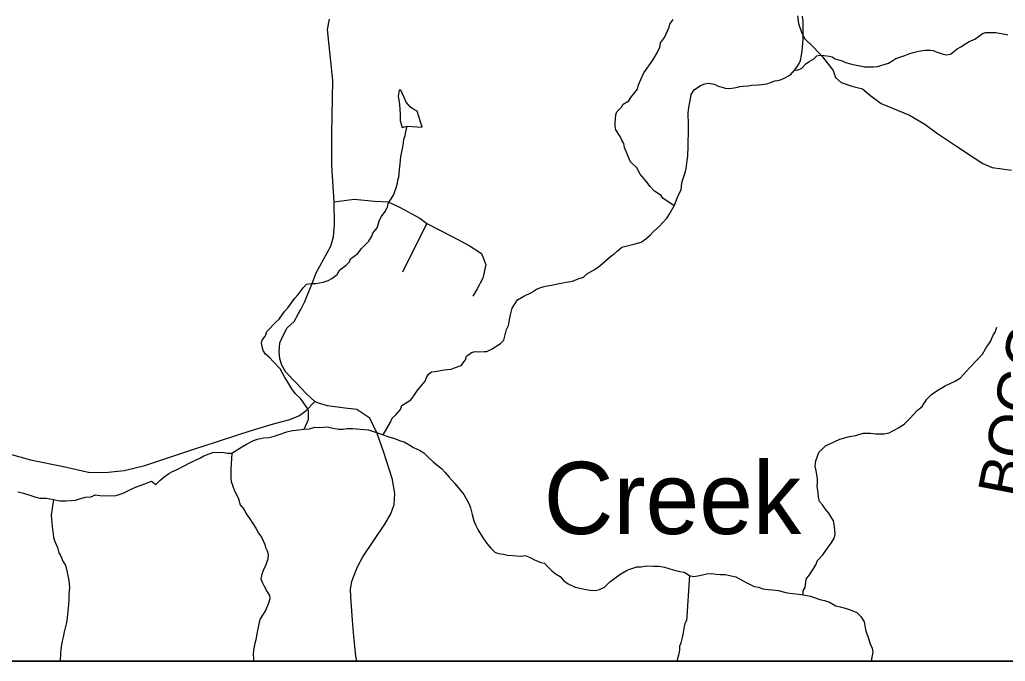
# Model space of a CAD drawing. Extents: x 0 to 39.3, y -3.9 to 22.
# Drawn here: x 4.806 to 6.099, y 13.9 to 14.741 of the extents above; entities that cross this region are included whole.
import ezdxf

# ---------------------------------------------------------------- set-up
doc = ezdxf.new("R2010")
doc.units = 0
for name, color, linetype in [('GM_X_Corporation', 7, 'Continuous'), ('GM_X_County_Road', 7, 'Continuous'), ('GM_X_Minor_Lake', 7, 'Continuous'), ('GM_X_Minor_River', 7, 'Continuous'), ('GM_X_Minor_River_Text', 7, 'Continuous'), ('GM_X_Township_Road', 7, 'Continuous'), ('GM_X_Township_Road_Text', 7, 'Continuous'), ('SH_Data', 7, 'Continuous')]:
    doc.layers.add(name, color=color, linetype=linetype)

msp = doc.modelspace()

# ---------------------------------------------------------------- linework, layer by layer
at = {"layer": 'GM_X_Corporation'}
msp.add_lwpolyline([(6.2667, 17.3782), (6.0256, 17.0319), (5.8398, 16.7652), (5.744, 16.6289), (5.7424, 16.6266), (5.2028, 15.8376), (5.0728, 15.652), (4.2376, 14.4362), (4.2334, 14.4302), (3.9536, 14.0228), (3.9474, 14.0138), (3.8692, 13.9), (7.894, 13.9)], dxfattribs=at)
at = {"layer": 'GM_X_County_Road'}
for points in [[(5.8265, 14.7467), (5.8278, 14.7364), (5.832, 14.724), (5.8363, 14.7165), (5.8473, 14.7053), (5.8593, 14.693), (5.8731, 14.6749), (5.8765, 14.6658), (5.8837, 14.659), (5.8977, 14.6544), (5.912, 14.6507), (5.9229, 14.6416), (5.9361, 14.6316), (5.9736, 14.6161), (5.9938, 14.6044), (6.0089, 14.5933), (6.0338, 14.5765), (6.0584, 14.5603), (6.0698, 14.5531), (6.0819, 14.5477), (6.1075, 14.544)], [(5.2484, 13.9), (5.2469, 13.9068), (5.2444, 13.9324), (5.2427, 13.9535), (5.2404, 13.9846), (5.2401, 13.9946), (5.2418, 14.0046), (5.2449, 14.0128), (5.2492, 14.0237), (5.2561, 14.0368), (5.2849, 14.0798), (5.2931, 14.0932), (5.2974, 14.1055), (5.2983, 14.1195), (5.2951, 14.1383), (5.2834, 14.1751), (5.2752, 14.1987), (5.2652, 14.219), (5.2563, 14.2252), (5.2484, 14.2301), (5.2327, 14.2321), (5.2096, 14.2349), (5.1982, 14.2386), (5.193, 14.2406), (5.1822, 14.2507), (5.1682, 14.2656), (5.1552, 14.2792), (5.1498, 14.2882), (5.1472, 14.2965), (5.1463, 14.3057), (5.1472, 14.3176), (5.1516, 14.3273), (5.1569, 14.3374), (5.1662, 14.3458), (5.1718, 14.356), (5.175, 14.3612), (5.1802, 14.3721), (5.1908, 14.3991), (5.1949, 14.4093), (5.2144, 14.4443), (5.2179, 14.4565), (5.2189, 14.4727), (5.2184, 14.5026), (5.2154, 14.5502), (5.2154, 14.5923), (5.2169, 14.6618), (5.2096, 14.7287), (5.2123, 14.7421)], [(4.7922, 14.172), (4.8202, 14.1642), (4.8632, 14.1554), (4.8981, 14.1478), (4.9219, 14.1479), (4.9432, 14.1504), (4.9703, 14.1569), (5.0357, 14.1786), (5.063, 14.1875), (5.0948, 14.1978), (5.1142, 14.2041), (5.139, 14.2115), (5.1602, 14.217), (5.1723, 14.2219), (5.1812, 14.2285), (5.193, 14.2406)]]:
    msp.add_lwpolyline(points, dxfattribs=at)
at = {"layer": 'GM_X_Minor_Lake'}
for points in [[(5.3145, 14.6017), (5.3342, 14.6006), (5.3273, 14.6216), (5.3217, 14.6247), (5.3187, 14.6267), (5.3131, 14.6332), (5.3109, 14.6386), (5.308, 14.6451), (5.3062, 14.649), (5.3039, 14.649), (5.3026, 14.641), (5.3043, 14.6304), (5.3053, 14.6174), (5.3051, 14.6094)], [(5.3051, 14.6094), (5.3076, 14.6003), (5.3145, 14.6017)]]:
    msp.add_lwpolyline(points, dxfattribs=at)
at = {"layer": 'GM_X_Minor_River'}
for points in [[(5.7459, 14.6525), (5.7509, 14.654), (5.7551, 14.6543), (5.7619, 14.6549), (5.7661, 14.6556), (5.7753, 14.6562), (5.7791, 14.6565), (5.7863, 14.6575), (5.7913, 14.659), (5.7967, 14.6612), (5.8005, 14.6619), (5.8055, 14.6629), (5.8116, 14.6662), (5.8174, 14.6692), (5.8232, 14.6759), (5.8267, 14.6804), (5.8287, 14.6842), (5.8303, 14.688), (5.8319, 14.6952), (5.8328, 14.7005), (5.8329, 14.7047), (5.8339, 14.7169), (5.834, 14.7267), (5.8338, 14.7328), (5.8339, 14.7385), (5.8332, 14.7462)], [(5.6647, 14.4975), (5.6496, 14.5073), (5.6478, 14.5111), (5.6391, 14.5166), (5.6332, 14.5228), (5.6276, 14.5301), (5.6201, 14.539), (5.6157, 14.5474), (5.6075, 14.5552), (5.6057, 14.559), (5.5995, 14.574), (5.5988, 14.5793), (5.5962, 14.5835), (5.594, 14.5885), (5.5881, 14.597), (5.5874, 14.6016), (5.5871, 14.6058), (5.5881, 14.6168), (5.5896, 14.6206), (5.5958, 14.6269), (5.5978, 14.6307), (5.6051, 14.6351), (5.6079, 14.6393), (5.6165, 14.6506), (5.6177, 14.6562), (5.6209, 14.663), (5.6248, 14.6717), (5.6369, 14.6883), (5.6424, 14.6981), (5.646, 14.7056), (5.6469, 14.7113), (5.6519, 14.7181), (5.6583, 14.7317), (5.6591, 14.7355), (5.6634, 14.7419)], [(5.8232, 14.6759), (5.8266, 14.6755), (5.8324, 14.6781), (5.8374, 14.6837), (5.8417, 14.6866), (5.8478, 14.6903), (5.8521, 14.6941), (5.8559, 14.6952), (5.8616, 14.6947), (5.8681, 14.6938), (5.8722, 14.6926), (5.876, 14.6902), (5.8851, 14.6874), (5.8896, 14.6854), (5.8961, 14.6834), (5.9036, 14.6818), (5.9086, 14.6809), (5.9143, 14.6797), (5.9264, 14.6795), (5.9314, 14.6802), (5.9459, 14.6845), (5.9517, 14.6882), (5.9556, 14.6904), (5.9674, 14.6944), (5.974, 14.6973), (5.9782, 14.6984), (5.9854, 14.7002), (5.9942, 14.7015), (6.0007, 14.7014), (6.0045, 14.701), (6.0086, 14.6994), (6.0162, 14.6966), (6.0215, 14.6953), (6.0272, 14.6964), (6.0361, 14.7035), (6.0407, 14.7057), (6.0481, 14.7109), (6.0519, 14.7127), (6.0592, 14.716), (6.0638, 14.7194), (6.0692, 14.7235), (6.0734, 14.7245), (6.0784, 14.7248), (6.0822, 14.7248), (6.0867, 14.7247), (6.0913, 14.7238), (6.0989, 14.7226), (6.1027, 14.7217)], [(5.2829, 14.1969), (5.2926, 14.2135), (5.2946, 14.2188), (5.2996, 14.2232), (5.3058, 14.2304), (5.3075, 14.2357), (5.3129, 14.239), (5.319, 14.2431), (5.3229, 14.248), (5.3284, 14.2559), (5.3338, 14.2622), (5.3381, 14.2675), (5.3397, 14.272), (5.3425, 14.2765), (5.3463, 14.2795), (5.3513, 14.2802), (5.3627, 14.2823), (5.3673, 14.2826), (5.3719, 14.2833), (5.3765, 14.2847), (5.3853, 14.288), (5.3911, 14.2955), (5.3924, 14.3001), (5.3986, 14.3049), (5.4035, 14.3063), (5.4085, 14.3059), (5.4153, 14.3061), (5.4191, 14.3064), (5.426, 14.3097), (5.4368, 14.3168), (5.4411, 14.3213), (5.4448, 14.3353), (5.4472, 14.3406), (5.4488, 14.3478), (5.4501, 14.3542), (5.4521, 14.3633), (5.4553, 14.3679), (5.4592, 14.3739), (5.4673, 14.3787), (5.4776, 14.3838), (5.4842, 14.3879), (5.4899, 14.3901), (5.4941, 14.3916), (5.498, 14.3926), (5.5037, 14.3933), (5.514, 14.3954), (5.5232, 14.3971), (5.5312, 14.3985), (5.5389, 14.4018), (5.5458, 14.404), (5.5496, 14.4077), (5.5612, 14.4144), (5.5673, 14.4188), (5.5813, 14.4308), (5.5859, 14.4345), (5.5898, 14.4379), (5.5959, 14.4431), (5.6063, 14.4456), (5.6116, 14.447), (5.6166, 14.4484), (5.6212, 14.4499), (5.6277, 14.4543), (5.6332, 14.4588), (5.637, 14.4633), (5.6459, 14.4712), (5.6494, 14.4749), (5.6553, 14.4817), (5.658, 14.4862), (5.6647, 14.4975), (5.6663, 14.5016), (5.6687, 14.5073), (5.6715, 14.5145), (5.6738, 14.5183), (5.6747, 14.5274), (5.6764, 14.5334), (5.6776, 14.5372), (5.6796, 14.5425), (5.6804, 14.5463), (5.6817, 14.5569), (5.6826, 14.5626), (5.6827, 14.5664), (5.6832, 14.5714), (5.6837, 14.6026), (5.6834, 14.6087), (5.6832, 14.614), (5.6832, 14.6186), (5.6833, 14.6239), (5.6846, 14.6311), (5.6859, 14.6379), (5.6871, 14.6433), (5.691, 14.6497), (5.6991, 14.6552), (5.7049, 14.6574), (5.7098, 14.6581), (5.7178, 14.6568), (5.7223, 14.6544), (5.7276, 14.6528), (5.7318, 14.6516), (5.7364, 14.6512), (5.7402, 14.6515), (5.7459, 14.6525)], [(5.1792, 14.2044), (5.1849, 14.2172), (5.1848, 14.229), (5.1829, 14.2328), (5.1781, 14.2398), (5.1744, 14.2448), (5.168, 14.2506), (5.1632, 14.2575), (5.1566, 14.2683), (5.154, 14.2722), (5.1477, 14.2837), (5.1387, 14.293), (5.1343, 14.298), (5.1286, 14.303), (5.1253, 14.3077), (5.1239, 14.3123), (5.1232, 14.3172), (5.124, 14.321), (5.1283, 14.3267), (5.1303, 14.3327), (5.1423, 14.3454), (5.1466, 14.3488), (5.1532, 14.3586), (5.1579, 14.3634), (5.1669, 14.3762), (5.1712, 14.3811), (5.1778, 14.3897), (5.1821, 14.3946), (5.1885, 14.3953), (5.1946, 14.3955), (5.2042, 14.3973), (5.2107, 14.3995), (5.2157, 14.402), (5.2223, 14.4073), (5.2262, 14.4133), (5.2343, 14.4196), (5.2389, 14.4241), (5.2401, 14.4279), (5.2498, 14.4349), (5.2545, 14.4413), (5.2642, 14.4511), (5.2681, 14.4575), (5.2693, 14.4616), (5.2748, 14.4684), (5.278, 14.4786), (5.2807, 14.4835), (5.2854, 14.4899), (5.2886, 14.4956), (5.2894, 14.5005), (5.2965, 14.5114), (5.2997, 14.5209), (5.3017, 14.5273), (5.3022, 14.5311), (5.3034, 14.5349), (5.3043, 14.5448), (5.3052, 14.5524), (5.3057, 14.5569), (5.3061, 14.5622), (5.3082, 14.5721), (5.3095, 14.5797), (5.31, 14.5846), (5.3116, 14.5896), (5.3124, 14.5945), (5.3145, 14.6017)], [(5.834, 13.9873), (5.8341, 13.9926), (5.8364, 13.9967), (5.8378, 14.0077), (5.8424, 14.0134), (5.8479, 14.022), (5.8507, 14.0265), (5.8527, 14.0322), (5.8597, 14.0397), (5.8667, 14.0495), (5.8706, 14.0551), (5.8745, 14.0615), (5.8758, 14.0664), (5.8755, 14.0718), (5.8752, 14.0767), (5.8738, 14.084), (5.8701, 14.0898), (5.8675, 14.0944), (5.8627, 14.0998), (5.8593, 14.1052), (5.8552, 14.1094), (5.8542, 14.1159), (5.8535, 14.1209), (5.8522, 14.1296), (5.8526, 14.1353), (5.8527, 14.1395), (5.8521, 14.1449), (5.851, 14.1498), (5.8496, 14.156), (5.8505, 14.1628), (5.8545, 14.1738), (5.8634, 14.1824), (5.868, 14.1846), (5.8753, 14.1882), (5.8822, 14.1915), (5.8899, 14.1937), (5.8948, 14.1948), (5.9032, 14.1961), (5.9082, 14.1979), (5.9132, 14.199), (5.9177, 14.1993), (5.9223, 14.1992), (5.9295, 14.1983), (5.9352, 14.1982), (5.9402, 14.1985), (5.9467, 14.1996), (5.9517, 14.2021), (5.9601, 14.2066), (5.9671, 14.2114), (5.9741, 14.2185), (5.9841, 14.2294), (5.9899, 14.2342), (5.9962, 14.2436), (6.0024, 14.25), (6.0105, 14.2556), (6.0201, 14.2611), (6.0332, 14.2673), (6.0405, 14.2718), (6.0444, 14.2763), (6.0521, 14.2849), (6.0622, 14.2954), (6.0692, 14.3029), (6.0747, 14.3119), (6.0798, 14.3194), (6.0834, 14.3278), (6.0857, 14.3315), (6.0881, 14.3383)], [(4.8033, 14.1222), (4.8108, 14.1205), (4.818, 14.1181), (4.8259, 14.1157), (4.8323, 14.1141), (4.8407, 14.1139), (4.8501, 14.1123), (4.8584, 14.1106), (4.8664, 14.1105), (4.8736, 14.1107), (4.8793, 14.1114), (4.8846, 14.1132), (4.8922, 14.1153), (4.8991, 14.1156), (4.9056, 14.1182), (4.9112, 14.1173), (4.9249, 14.1171), (4.9325, 14.1173), (4.9416, 14.1206), (4.9504, 14.125), (4.958, 14.1283), (4.9653, 14.1312), (4.9725, 14.1337), (4.979, 14.1363), (4.9846, 14.132), (4.9896, 14.1369), (4.995, 14.1413), (5.0016, 14.1462), (5.0065, 14.1488), (5.0119, 14.1509), (5.0218, 14.1565), (5.0291, 14.1601), (5.0421, 14.1664), (5.0474, 14.1693), (5.0547, 14.1723), (5.0608, 14.1741), (5.0665, 14.174), (5.0725, 14.1742), (5.0782, 14.173), (5.0843, 14.1729), (5.0981, 14.1818), (5.1034, 14.1847), (5.1126, 14.1895), (5.1179, 14.1913), (5.1259, 14.1931), (5.1328, 14.1937), (5.14, 14.1951), (5.1465, 14.1973), (5.1564, 14.2009), (5.164, 14.2027), (5.1689, 14.203), (5.1792, 14.2044), (5.1864, 14.205), (5.1933, 14.2072), (5.1982, 14.2067), (5.2043, 14.207), (5.2092, 14.2073), (5.2149, 14.2064), (5.2243, 14.2043), (5.2304, 14.2046), (5.2353, 14.2053), (5.2429, 14.2052), (5.2527, 14.2046), (5.2584, 14.2042), (5.2637, 14.2037), (5.2743, 14.2001), (5.2829, 14.1969), (5.2905, 14.1945), (5.2976, 14.1921), (5.3055, 14.1893), (5.3105, 14.1877), (5.3157, 14.1849), (5.3228, 14.1806), (5.3304, 14.1771), (5.336, 14.1732), (5.3416, 14.1682), (5.3483, 14.1616), (5.3532, 14.1577), (5.3595, 14.1527), (5.3644, 14.1476), (5.3696, 14.1415), (5.377, 14.133), (5.383, 14.1257), (5.3889, 14.1187), (5.3926, 14.1118), (5.3959, 14.1061), (5.3973, 14.1011), (5.3995, 14.0927), (5.402, 14.0843), (5.4045, 14.0782), (5.4071, 14.0728), (5.4111, 14.0663), (5.4141, 14.0613), (5.4189, 14.0544), (5.4241, 14.0482), (5.4293, 14.0432)], [(5.0843, 14.1729), (5.0829, 14.152), (5.0831, 14.1447), (5.083, 14.1398), (5.0834, 14.1356), (5.0877, 14.1237), (5.0903, 14.1187), (5.0932, 14.113), (5.0954, 14.1053), (5.1006, 14.0991), (5.1031, 14.0934), (5.108, 14.0868), (5.1157, 14.0745), (5.1194, 14.068), (5.1231, 14.063), (5.1257, 14.0572), (5.1275, 14.053), (5.1286, 14.0492), (5.1308, 14.045), (5.1319, 14.0404), (5.1314, 14.0339), (5.1298, 14.029), (5.1286, 14.0252), (5.1262, 14.0211), (5.1238, 14.0143), (5.1222, 14.0082), (5.124, 14.0036), (5.1269, 13.9986), (5.1306, 13.9909), (5.1336, 13.9863), (5.1342, 13.9821), (5.1322, 13.9764), (5.1283, 13.9666), (5.1247, 13.9606), (5.1216, 13.9557), (5.12, 13.9511), (5.1175, 13.9382), (5.1166, 13.9337), (5.1162, 13.9299), (5.1145, 13.9235), (5.1137, 13.9193), (5.1128, 13.9144), (5.1124, 13.9087), (5.1127, 13.9045), (5.1126, 13.9007), (5.1137, 13.9)], [(4.8501, 14.1123), (4.8473, 14.0917), (4.8476, 14.0867), (4.8483, 14.0814), (4.8489, 14.073), (4.8499, 14.0677), (4.8502, 14.0623), (4.852, 14.0573), (4.8557, 14.0493), (4.8571, 14.0424), (4.8593, 14.0386), (4.863, 14.0305), (4.8659, 14.0259), (4.8677, 14.0186), (4.8687, 14.0141), (4.8705, 14.006), (4.8708, 14.0011), (4.8711, 13.9969), (4.8706, 13.9878), (4.8704, 13.9802), (4.8699, 13.9744), (4.8695, 13.9699), (4.8685, 13.9612), (4.8677, 13.9536), (4.8668, 13.949), (4.8656, 13.9437), (4.8643, 13.9388), (4.8631, 13.9316), (4.8615, 13.9266), (4.861, 13.9221), (4.8597, 13.9153), (4.8593, 13.9111), (4.8591, 13.9), (4.8591, 13.9)], [(5.4293, 14.0432), (5.4342, 14.0412), (5.4407, 14.0407), (5.4459, 14.0391), (5.4528, 14.0386), (5.4577, 14.0381), (5.4634, 14.038), (5.4691, 14.0387), (5.4758, 14.0363), (5.4815, 14.0332), (5.4898, 14.0296), (5.4947, 14.0288), (5.4991, 14.0238), (5.504, 14.0187), (5.51, 14.0141), (5.5149, 14.0113), (5.5201, 14.0055), (5.5257, 14.0016), (5.5347, 13.9973), (5.5408, 13.9961), (5.5464, 13.9948), (5.5544, 13.9932), (5.5616, 13.9927), (5.5669, 13.9941), (5.5734, 13.9974), (5.5803, 14.0041), (5.5888, 14.0105), (5.5949, 14.0149), (5.6029, 14.0197), (5.6079, 14.0212), (5.6155, 14.0237), (5.6212, 14.024), (5.6281, 14.0254), (5.6375, 14.0248), (5.6451, 14.0247), (5.6519, 14.0234), (5.6576, 14.0215), (5.6632, 14.0198), (5.6723, 14.0178), (5.6776, 14.0169), (5.6847, 14.0126), (5.69, 14.0114), (5.6957, 14.0121), (5.7018, 14.0135), (5.7071, 14.0145), (5.7143, 14.0152), (5.72, 14.0143), (5.7253, 14.0138), (5.7317, 14.0137), (5.7457, 14.0108), (5.7544, 14.0061), (5.7592, 14.0034), (5.7698, 13.9979), (5.7754, 13.997), (5.7811, 13.995), (5.7879, 13.9942), (5.7943, 13.9937), (5.8011, 13.9928), (5.8128, 13.9899), (5.8204, 13.989), (5.828, 13.9882), (5.834, 13.9873), (5.8435, 13.9852), (5.8495, 13.9832), (5.8559, 13.9812), (5.8619, 13.9796), (5.8687, 13.9776), (5.8766, 13.9729), (5.8827, 13.9713), (5.8891, 13.9696), (5.8943, 13.9677), (5.8992, 13.966), (5.9045, 13.9641), (5.9094, 13.9587), (5.9142, 13.9517), (5.9159, 13.9414), (5.9177, 13.9361), (5.9191, 13.9311), (5.922, 13.9231), (5.9246, 13.917), (5.9253, 13.912), (5.9236, 13.9033), (5.9234, 13.9)], [(5.6847, 14.0126), (5.6812, 13.959), (5.6807, 13.9537), (5.6787, 13.9496), (5.6779, 13.9454), (5.6762, 13.9351), (5.675, 13.931), (5.6733, 13.9242), (5.6717, 13.9196), (5.6716, 13.9147), (5.6704, 13.9082), (5.6684, 13.9)]]:
    msp.add_lwpolyline(points, dxfattribs=at)
at = {"layer": 'GM_X_Township_Road'}
msp.add_line((5.3086, 14.4108), (5.3401, 14.4742), dxfattribs=at)
msp.add_lwpolyline([(5.2184, 14.5026), (5.2448, 14.5061), (5.2716, 14.5036), (5.2894, 14.5026), (5.3051, 14.495), (5.3198, 14.4874), (5.3309, 14.4813), (5.3401, 14.4742), (5.3725, 14.4575), (5.3958, 14.4453), (5.412, 14.4347), (5.4176, 14.4205), (5.4136, 14.4027), (5.406, 14.3885), (5.4004, 14.3789)], dxfattribs=at)
at = {"layer": 'SH_Data'}
msp.add_lwpolyline([(1.9, 21.1), (9.1, 21.1), (9.1, 13.9), (1.9, 13.9)], close=True, dxfattribs=at)

# ---------------------------------------------------------------- texts
at = {"layer": 'GM_X_Minor_River_Text'}
msp.add_text('Creek', height=0.09469, rotation=0.0017, dxfattribs=at).set_placement((5.4936, 14.0669))
at = {"layer": 'GM_X_Township_Road_Text'}
msp.add_text('BOGGS', height=0.05682, rotation=78.9686, dxfattribs=at).set_placement((6.1186, 14.1123))

doc.saveas('drawing.dxf')
